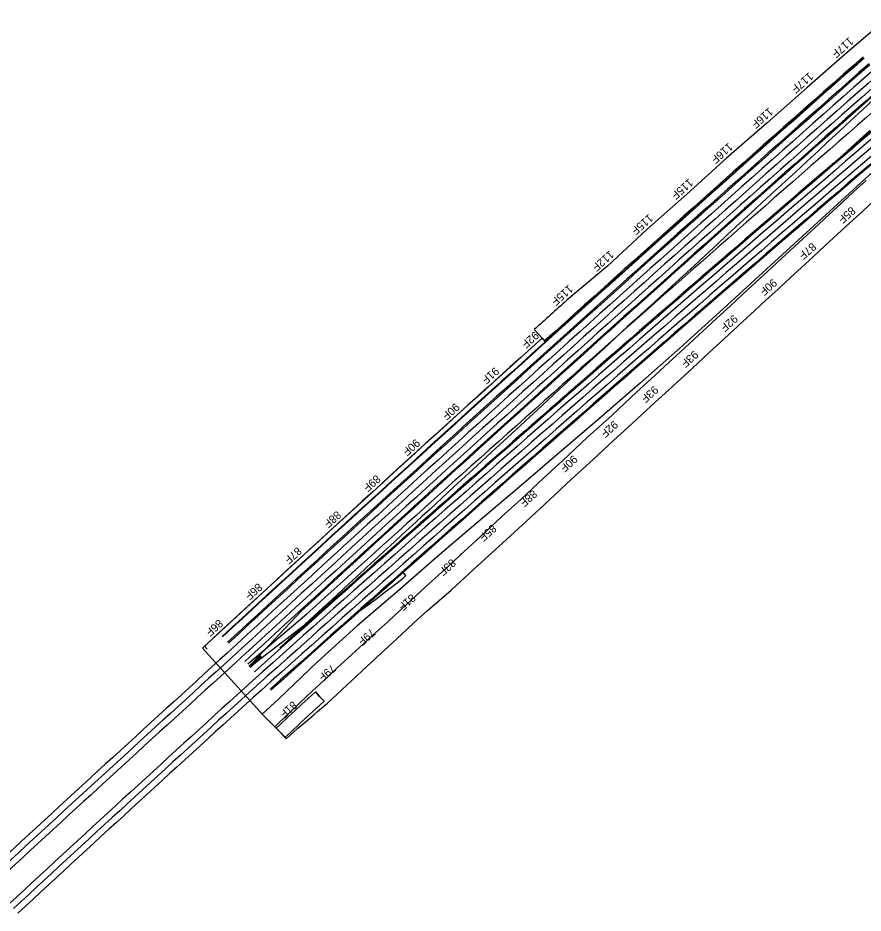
# Model space of a CAD drawing. Extents: x 2163396 to 2173129, y 605545 to 614595.
# Drawn here: x 2167972 to 2169556, y 609850 to 611528 of the extents above; entities that cross this region are included whole.
import ezdxf

# ---------------------------------------------------------------- set-up
doc = ezdxf.new("R2010")
doc.units = 0
for name, color, linetype in [('RD_PD_AsphRem', 7, 'Continuous'), ('RD_PD_CstnLmt', 7, 'Continuous'), ('RD_PD_EarthShd', 7, 'Continuous'), ('RD_PD_Final_LnLine', 7, 'Continuous'), ('RD_PD_Final_TrvlWay', 7, 'Continuous'), ('RD_PD_GR', 7, 'Continuous'), ('RD_PD_MedBWall', 7, 'Continuous'), ('RD_PD_MedGR', 7, 'Continuous'), ('RD_PD_TX_CstnLmt', 7, 'Continuous'), ('RD_PD_WallFill', 7, 'Continuous')]:
    doc.layers.add(name, color=color, linetype=linetype)

msp = doc.modelspace()

# ---------------------------------------------------------------- linework, layer by layer
at = {"layer": 'RD_PD_AsphRem'}
for p, q in [((2168529.4, 610264.8), (2168516, 610252.5)), ((2168516, 610252.5), (2168504.2, 610241.5)), ((2168531.5, 610234.1), (2168545.6, 610247.2)), ((2168504.2, 610241.5), (2168491.5, 610229.8)), ((2168461.3, 610201.9), (2168456, 610197))]:
    msp.add_line(p, q, dxfattribs=at)
for points in [[(2169576.6, 611375.3), (2169555.2, 611355.6), (2169533.3, 611335.3), (2169511.7, 611315.4), (2169490.9, 611296), (2169471.7, 611278.2), (2169451.2, 611259.2), (2169428.7, 611238.2), (2169409.9, 611221), (2169390.3, 611203), (2169367.2, 611181.7), (2169345.8, 611161.8), (2169325.4, 611142.9), (2169302.2, 611121.8), (2169283.2, 611103.8), (2169259.6, 611082), (2169240, 611063.6), (2169219.6, 611045.1), (2169196.9, 611024.2), (2169175.3, 611004.3), (2169156.8, 610987.3), (2169141, 610972.9), (2169130.1, 610963), (2169114.8, 610949.2), (2169070, 610907.7), (2169030.7, 610871.8), (2168986.7, 610831.2), (2168954.6, 610801.5), (2168922.8, 610772), (2168888.9, 610740.8), (2168859.4, 610713.7), (2168823.8, 610680.8), (2168789.9, 610649.3), (2168766.2, 610627.5), (2168744.3, 610607.2), (2168729.6, 610593.9), (2168710.1, 610576), (2168693.6, 610560.6), (2168677.2, 610545.3), (2168657.4, 610527.1), (2168639, 610510.2), (2168626.8, 610498.9), (2168620.7, 610493.2), (2168600.4, 610474.6), (2168581.6, 610457), (2168568.4, 610444.9), (2168549.3, 610427.3), (2168536.1, 610415.2), (2168519.9, 610400.3), (2168508.6, 610389.7), (2168495.8, 610377.9), (2168486.5, 610369.2), (2168478.1, 610361.3), (2168468.5, 610352.5), (2168462.9, 610347.3)], [(2169518.5, 611270.4), (2169543.2, 611293.5), (2169568.7, 611316.9)], [(2169561.7, 611223.1), (2169538.4, 611201.7), (2169516.3, 611181.1), (2169494.1, 611160.6), (2169473.1, 611141.1), (2169451.4, 611121.3), (2169427.5, 611099), (2169402.7, 611076.3), (2169377.1, 611052.6), (2169354.6, 611031.7), (2169330.7, 611009.7), (2169306.7, 610987.5), (2169282, 610964.8), (2169255.3, 610940.2), (2169239.2, 610925.4), (2169213.7, 610901.9), (2169184.4, 610874.9), (2169173.5, 610864.7), (2169131.6, 610826.1), (2169085.5, 610783.5), (2169039.2, 610741.2), (2168993.2, 610698.2), (2168957.3, 610665.4), (2168915, 610626.1), (2168879.2, 610593.3), (2168845.8, 610562.4), (2168808.9, 610528.3), (2168772.9, 610494.8), (2168742.4, 610467.1), (2168718.2, 610445), (2168690.8, 610419.9), (2168679.2, 610409.1), (2168665.2, 610396), (2168643.6, 610376.7), (2168620.2, 610355.2), (2168597.4, 610334.3), (2168570.4, 610309.7), (2168544.7, 610285.6), (2168523.9, 610266.4), (2168500.4, 610244), (2168480.9, 610225.6), (2168471.4, 610216.5), (2168461.6, 610207), (2168453.7, 610199.4), (2168456, 610197)], [(2168472.3, 610179.3), (2168473.9, 610177.6), (2168474.6, 610177), (2168482.7, 610184.4), (2168489, 610189.8), (2168496.7, 610196.5), (2168513.5, 610210.6), (2168526.8, 610221.7), (2168533.5, 610227.7), (2168545.2, 610238.1), (2168552, 610243.7), (2168560.7, 610251.6), (2168588.4, 610277.3), (2168616.2, 610303.3), (2168643.7, 610329.1), (2168674, 610356.9), (2168700.7, 610381.6), (2168714.8, 610394.8), (2168739, 610416.5), (2168783.7, 610455.5), (2168833.1, 610500.8), (2168880, 610543.5), (2168925.2, 610584.6), (2168968.3, 610624.4), (2169009.8, 610663.1), (2169050.2, 610700.3), (2169088.2, 610736), (2169115.3, 610760.4), (2169166.6, 610807.4), (2169197.5, 610835.8), (2169208.3, 610845.8), (2169226.7, 610862.8), (2169246.6, 610880.9), (2169267, 610899.8), (2169288.4, 610919.5), (2169312.1, 610941.5), (2169330.6, 610958.5), (2169353.1, 610979.2), (2169374.1, 610998.6), (2169396.9, 611019.6), (2169419.5, 611040.6), (2169440.7, 611060), (2169462.4, 611080.1), (2169484.6, 611100.7), (2169508.4, 611122.5), (2169531.2, 611143.6), (2169556, 611166.4), (2169578.6, 611187.4)], [(2168613.5, 610417), (2168630.9, 610429.8), (2168645, 610440), (2168660.1, 610451.9), (2168674.7, 610463), (2168693.9, 610477.9), (2168698.4, 610482), (2168698.7, 610482.9), (2168695.1, 610487), (2168693.9, 610488.3)], [(2168462.9, 610347.3), (2168462.9, 610347.3)], [(2168456, 610197), (2168461.3, 610201.9), (2168478.5, 610217.7), (2168491.5, 610229.8), (2168504.2, 610241.5), (2168516, 610252.5), (2168529.4, 610264.8), (2168537.4, 610255.9), (2168545.6, 610247.2), (2168531.5, 610234.1), (2168510.4, 610214.6), (2168499.3, 610204.3), (2168483.3, 610189.4), (2168472.3, 610179.3)], [(2168545.6, 610247.2), (2168537.4, 610255.9), (2168529.4, 610264.8)], [(2168491.5, 610229.8), (2168478.5, 610217.7), (2168461.3, 610201.9)], [(2168499.3, 610204.3), (2168510.4, 610214.6), (2168531.5, 610234.1)], [(2168456, 610197), (2168464.4, 610187.9), (2168464.6, 610187.7), (2168472.3, 610179.3)], [(2168472.3, 610179.3), (2168483.3, 610189.4), (2168499.3, 610204.3)]]:
    msp.add_lwpolyline(points, dxfattribs=at)
for radius, start, end in [(72980.2, 130.620048, 131.720963), (72932.2, 131.511785, 131.596222)]:
    msp.add_arc((2217031.5, 555875.3), radius, start, end, dxfattribs=at)
at = {"layer": 'RD_PD_CstnLmt'}
for p, q in [((2169602.2, 611527.6), (2169526.2, 611462.6)), ((2169526.2, 611462.6), (2169450.8, 611396.6)), ((2169450.8, 611396.6), (2169375.6, 611330.5)), ((2169375.6, 611330.5), (2169300.2, 611264.6)), ((2169300.2, 611264.6), (2169225.8, 611197.6)), ((2169582, 611246), (2169508, 611178.9)), ((2169225.8, 611197.6), (2169150.8, 611131.1)), ((2169508, 611178.9), (2169434.3, 611111.4)), ((2169150.8, 611131.1), (2169077.5, 611062.9)), ((2169434.3, 611111.4), (2169360.8, 611043.7)), ((2169077.5, 611062.9), (2169000.7, 610998.5)), ((2169360.8, 611043.7), (2169287.2, 610976.2)), ((2169287.2, 610976.2), (2169213.2, 610909.1)), ((2168954.3, 610927.4), (2168939.7, 610943.6)), ((2169213.2, 610909.1), (2169138.3, 610843.1)), ((2169138.3, 610843.1), (2169062.8, 610777.7)), ((2169062.8, 610777.7), (2168986.7, 610712.9)), ((2168986.7, 610712.9), (2168911, 610647.8)), ((2168911, 610647.8), (2168834.7, 610583.3)), ((2168834.7, 610583.3), (2168758.6, 610518.5)), ((2168758.6, 610518.5), (2168683.3, 610452.9)), ((2168683.3, 610452.9), (2168607.4, 610387.9)), ((2168607.4, 610387.9), (2168533.4, 610320.7)), ((2168431.7, 610221.2), (2168317.6, 610346.7)), ((2168533.4, 610320.7), (2168461, 610251.9)), ((2168461, 610251.9), (2168429.9, 610223.2)), ((2168431.7, 610221.2), (2168453.7, 610199.4))]:
    msp.add_line(p, q, dxfattribs=at)
for points in [[(2168472.3, 610179.3), (2168473.9, 610177.6), (2168474.6, 610177), (2168482.7, 610184.4), (2168489, 610189.8), (2168496.7, 610196.5), (2168513.5, 610210.6), (2168526.8, 610221.7), (2168533.5, 610227.7), (2168545.2, 610238.1), (2168552, 610243.7), (2168560.7, 610251.6), (2168588.4, 610277.3), (2168616.2, 610303.3), (2168643.7, 610329.1), (2168674, 610356.9), (2168700.7, 610381.6), (2168714.8, 610394.8), (2168739, 610416.5), (2168783.7, 610455.5), (2168833.1, 610500.8), (2168880, 610543.5), (2168925.2, 610584.6), (2168968.3, 610624.4), (2169009.8, 610663.1), (2169050.2, 610700.3), (2169088.2, 610736), (2169115.3, 610760.4), (2169166.6, 610807.4), (2169197.5, 610835.8), (2169208.3, 610845.8), (2169226.7, 610862.8), (2169246.6, 610880.9), (2169267, 610899.8), (2169288.4, 610919.5), (2169312.1, 610941.5), (2169330.6, 610958.5), (2169353.1, 610979.2), (2169374.1, 610998.6), (2169396.9, 611019.6), (2169419.5, 611040.6), (2169440.7, 611060), (2169462.4, 611080.1), (2169484.6, 611100.7), (2169508.4, 611122.5), (2169531.2, 611143.6), (2169556, 611166.4), (2169578.6, 611187.4)], [(2168453.7, 610199.4), (2168456, 610197), (2168460.2, 610192.5), (2168464.4, 610187.9), (2168468.5, 610183.5), (2168472.3, 610179.3), (2168473.1, 610178.5), (2168473.9, 610177.6), (2168474.2, 610177.3), (2168474.6, 610177)]]:
    msp.add_lwpolyline(points, dxfattribs=at)
for radius, start, end in [(73111.5, 131.966747, 132.03105), (73089.7, 132.03105, 132.706613)]:
    msp.add_arc((2217890.3, 556637.7), radius, start, end, dxfattribs=at)
at = {"layer": 'RD_PD_EarthShd'}
for p, q in [((2168503.7, 610416.8), (2168411.8, 610319.2)), ((2168519.8, 610398), (2168414.1, 610316.7))]:
    msp.add_line(p, q, dxfattribs=at)
for centre, radius, start, end in [((2217890.3, 556637.7), 73082.7, 131.403882, 132.031087), ((2217890.3, 556637.7), 73015.3, 131.404285, 132.56198), ((2217031.5, 555875.3), 72980.2, 130.502969, 131.661178), ((2217031.5, 555875.3), 72932.2, 130.502672, 131.772193)]:
    msp.add_arc(centre, radius, start, end, dxfattribs=at)
at = {"layer": 'RD_PD_Final_LnLine'}
for centre, radius, start, end in [((2217890.3, 556637.7), 73079.7, 131.403889, 132.673453), ((2217890.3, 556637.7), 73065.7, 131.403889, 132.673536), ((2217890.3, 556637.7), 73051.3, 131.404063, 132.684686), ((2217890.3, 556637.7), 73039.3, 131.404137, 132.684757), ((2217890.3, 556637.7), 73027.3, 131.404211, 132.684829), ((2217031.5, 555875.3), 72968.2, 130.502895, 131.783502), ((2217031.5, 555875.3), 72956.2, 130.502821, 131.783426), ((2217031.5, 555875.3), 72944.2, 130.502746, 131.783349), ((2217463.6, 556252.9), 73047.2, 132.234052, 132.719474), ((2217463.6, 556252.9), 73035.2, 132.23405, 132.719474), ((2217463.6, 556252.9), 73023.2, 132.234047, 132.719474), ((2217463.6, 556252.9), 72976.8, 132.234037, 132.719474), ((2217463.6, 556252.9), 72964.8, 132.234034, 132.719474), ((2217463.6, 556252.9), 72952.8, 132.234032, 132.719474)]:
    msp.add_arc(centre, radius, start, end, dxfattribs=at)
at = {"layer": 'RD_PD_Final_TrvlWay'}
for centre, radius, start, end in [((2217890.3, 556637.7), 73080.7, 131.403882, 132.673447), ((2217890.3, 556637.7), 73017.3, 131.404285, 132.673836), ((2217031.5, 555875.3), 72978.2, 130.502969, 131.772513), ((2217031.5, 555875.3), 72934.2, 130.502672, 131.772206)]:
    msp.add_arc(centre, radius, start, end, dxfattribs=at)
at = {"layer": 'RD_PD_GR'}
msp.add_line((2168402.9, 610317.4), (2168513.2, 610410.7), dxfattribs=at)
msp.add_arc((2217463.6, 556252.9), 73001.5, 130.953509, 132.108774, dxfattribs=at)
at = {"layer": 'RD_PD_MedBWall'}
for radius, start, end in [(73065.7, 131.403975, 132.673536), (73063.3, 131.404063, 132.67355)]:
    msp.add_arc((2217890.3, 556637.7), radius, start, end, dxfattribs=at)
at = {"layer": 'RD_PD_MedGR'}
for p, q in [((2168405.2, 610313.2), (2168425.2, 610331.3)), ((2168425.2, 610331.3), (2168405.2, 610313.2)), ((2168407.5, 610310.7), (2168427.5, 610328.9)), ((2168407.5, 610310.7), (2168427.5, 610328.9)), ((2168408.5, 610315.5), (2168425.6, 610331)), ((2168410.1, 610313.8), (2168427.1, 610329.2)), ((2168421.1, 610326.9), (2168422.7, 610325.2)), ((2168421.4, 610327.2), (2168423, 610325.5)), ((2168424.9, 610327.2), (2168423, 610325.5)), ((2168423.3, 610329), (2168424.9, 610327.2)), ((2168423.6, 610329.2), (2168425.2, 610327.5)), ((2168425.2, 610331.3), (2168427.5, 610328.9)), ((2168425.2, 610331.3), (2168425.5, 610331)), ((2168427.2, 610329.2), (2168427.5, 610328.9)), ((2168405.2, 610313.2), (2168405.6, 610312.8)), ((2168405.2, 610313.2), (2168405.6, 610312.8)), ((2168405.6, 610312.8), (2168408.5, 610315.5)), ((2168405.6, 610312.8), (2168408.5, 610315.5)), ((2168407.1, 610311.1), (2168410.1, 610313.8)), ((2168410.1, 610313.8), (2168407.1, 610311.1)), ((2168407.5, 610310.7), (2168407.1, 610311.1)), ((2168407.1, 610311.1), (2168407.5, 610310.7)), ((2168408.5, 610315.5), (2168410.1, 610313.8)), ((2168410, 610316.8), (2168411.6, 610315.1)), ((2168411.6, 610315.1), (2168410.1, 610313.8)), ((2168410.3, 610317.1), (2168411.9, 610315.4)), ((2168411.9, 610315.4), (2168411.6, 610315.1)), ((2168413.8, 610317.1), (2168411.9, 610315.4)), ((2168412.2, 610318.9), (2168413.8, 610317.1)), ((2168412.5, 610319.1), (2168414.1, 610317.4)), ((2168414.1, 610317.4), (2168413.8, 610317.1)), ((2168416, 610319.2), (2168414.1, 610317.4)), ((2168414.5, 610320.9), (2168416, 610319.2)), ((2168414.8, 610321.2), (2168416.3, 610319.4)), ((2168416.3, 610319.4), (2168416, 610319.2)), ((2168418.2, 610321.2), (2168416.3, 610319.4)), ((2168416.7, 610322.9), (2168418.2, 610321.2)), ((2168417, 610323.2), (2168418.5, 610321.4)), ((2168418.5, 610321.4), (2168418.2, 610321.2)), ((2168420.5, 610323.2), (2168418.5, 610321.4)), ((2168418.9, 610324.9), (2168420.5, 610323.2)), ((2168419.2, 610325.2), (2168420.8, 610323.5)), ((2168420.8, 610323.5), (2168420.5, 610323.2)), ((2168422.7, 610325.2), (2168420.8, 610323.5)), ((2168423, 610325.5), (2168422.7, 610325.2))]:
    msp.add_line(p, q, dxfattribs=at)
for points in [[(2168408.5, 610315.5), (2168410, 610316.8), (2168410.3, 610317.1), (2168412.2, 610318.9), (2168412.5, 610319.1), (2168414.5, 610320.9), (2168414.8, 610321.2), (2168416.7, 610322.9), (2168417, 610323.2), (2168418.9, 610324.9), (2168419.2, 610325.2), (2168421.1, 610326.9), (2168421.4, 610327.2), (2168423.3, 610329), (2168423.6, 610329.2), (2168425.6, 610331)], [(2168427.1, 610329.2), (2168425.2, 610327.5), (2168424.9, 610327.2)], [(2168425.6, 610331), (2168425.5, 610331), (2168425.2, 610331.3)], [(2168427.5, 610328.9), (2168427.2, 610329.2), (2168427.1, 610329.2)]]:
    msp.add_lwpolyline(points, dxfattribs=at)
for radius in [1.67, 1.67, 1.27, 1.27]:
    msp.add_arc((2168426.3, 610330.1), radius, 312.2497, 132.2497, dxfattribs=at)
at = {"layer": 'RD_PD_WallFill'}
for p, q in [((2168954.3, 610927.4), (2168960.3, 610920.6)), ((2168321.6, 610350.3), (2168326.5, 610345))]:
    msp.add_line(p, q, dxfattribs=at)
msp.add_arc((2217890.3, 556637.7), 73089.7, 132.03105, 132.702363, dxfattribs=at)

# ---------------------------------------------------------------- texts
at = {"layer": 'RD_PD_TX_CstnLmt'}
for s, rotation, p in [('117F', 220.9671, (2169530.2, 611492.6)), ('117F', 221.0456, (2169454.8, 611426.6)), ('116F', 221.1241, (2169379.5, 611360.5)), ('116F', 221.2026, (2169304.1, 611294.6)), ('115F', 221.281, (2169229.6, 611227.5)), ('85F', 221.1241, (2169534, 611175)), ('115F', 221.3595, (2169154.6, 611161.1)), ('87F', 221.2026, (2169460.3, 611107.5)), ('112F', 221.438, (2169081.2, 611092.9)), ('90F', 221.281, (2169386.8, 611039.9)), ('115F', 221.5165, (2169004.4, 611028.5)), ('92F', 221.3595, (2169313.2, 610972.4)), ('92F', 221.595, (2168940.2, 610941.4)), ('93F', 221.438, (2169239.2, 610905.3)), ('91F', 221.6735, (2168865.8, 610874.3)), ('93F', 221.5165, (2169164.3, 610839.4)), ('90F', 221.752, (2168791.6, 610807.1)), ('92F', 221.595, (2169088.7, 610774)), ('90F', 221.8305, (2168717.4, 610739.8)), ('90F', 221.6735, (2169012.7, 610709.3)), ('89F', 221.9089, (2168643.3, 610672.4)), ('88F', 221.752, (2168937, 610644.2)), ('88F', 221.9874, (2168569.4, 610604.9)), ('85F', 221.8305, (2168860.7, 610579.7)), ('87F', 222.0659, (2168495.5, 610537.2)), ('83F', 221.9089, (2168784.6, 610515)), ('86F', 222.1444, (2168421.7, 610469.5)), ('81F', 221.9874, (2168709.3, 610449.4)), ('86F', 222.2229, (2168348, 610401.7)), ('79F', 222.0659, (2168633.4, 610384.4)), ('79F', 222.1444, (2168559.5, 610317.3)), ('81F', 222.2229, (2168487, 610248.5))]:
    msp.add_text(s, height=15, rotation=rotation, dxfattribs=at).set_placement(p)

doc.saveas('drawing.dxf')
